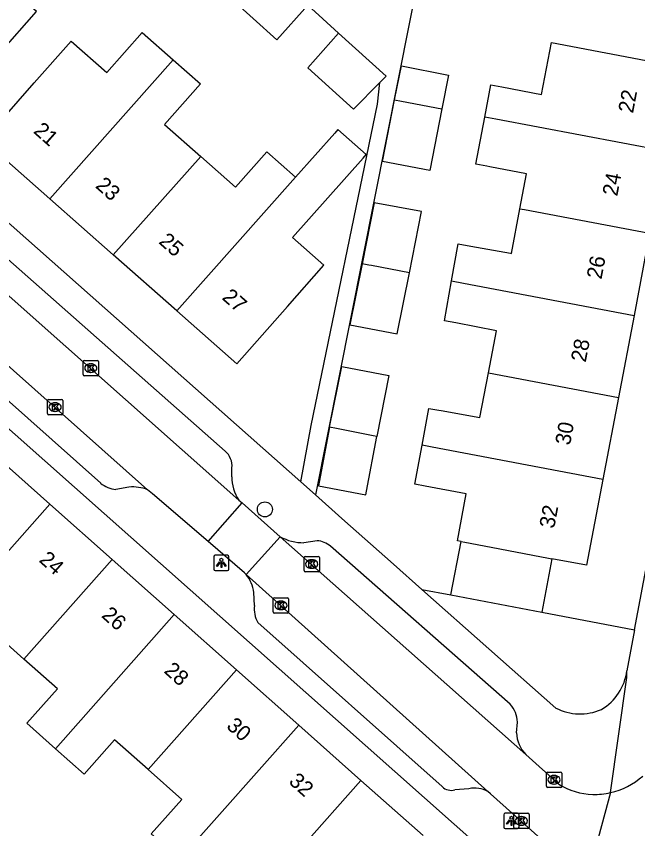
# Model space of a CAD drawing. Extents: x 163150 to 163546, y 380933 to 381635.
# Drawn here: x 163394.1 to 163434.7, y 381038.6 to 381091.7 of the extents above; entities that cross this region are included whole.
import ezdxf

# ---------------------------------------------------------------- set-up
doc = ezdxf.new("R2010")
doc.units = 0
for name, color, linetype in [('IMGEO_Boom', 7, 'Continuous'), ('IMGEO_Groenvoorziening', 7, 'Continuous'), ('IMGEO_Kolk', 7, 'Continuous'), ('IMGEO_Lichtpunt', 7, 'Continuous'), ('IMGEO_Muur', 7, 'Continuous'), ('IMGEO_Pand', 7, 'Continuous'), ('IMGEO_Pand_nummerreeks', 7, 'Continuous'), ('IMGEO_Rijbaan_lokaal_open', 7, 'Continuous'), ('IMGEO_Voetpad_open', 7, 'Continuous')]:
    doc.layers.add(name, color=color, linetype=linetype)

msp = doc.modelspace()

# ---------------------------------------------------------------- linework, layer by layer
at = {"layer": 'IMGEO_Boom'}
msp.add_circle((163410.34, 381059.48), 0.489, dxfattribs=at)
at = {"layer": 'IMGEO_Groenvoorziening'}
for points in [[(163420.6, 381054.259), (163422.486, 381053.901)], [(163428.425, 381052.773), (163434.486, 381051.622)]]:
    msp.add_lwpolyline(points, dxfattribs=at)
at = {"layer": 'IMGEO_Kolk'}
for p, q in [((163398.475, 381068.275), (163398.475, 381069.127)), ((163398.55, 381069.201), (163399.402, 381069.201)), ((163398.963, 381068.981), (163398.988, 381068.981)), ((163399.476, 381069.127), (163399.476, 381068.275)), ((163398.986, 381068.421), (163398.961, 381068.421)), ((163399.402, 381068.201), (163398.55, 381068.201)), ((163396.142, 381065.73), (163396.142, 381066.582)), ((163396.217, 381066.656), (163397.069, 381066.656)), ((163396.63, 381066.436), (163396.655, 381066.436)), ((163397.143, 381066.582), (163397.143, 381065.73)), ((163396.653, 381065.876), (163396.628, 381065.876)), ((163397.069, 381065.656), (163396.217, 381065.656)), ((163412.897, 381055.49), (163412.897, 381056.342)), ((163412.972, 381056.416), (163413.824, 381056.416)), ((163413.385, 381056.196), (163413.41, 381056.196)), ((163413.898, 381056.342), (163413.898, 381055.49)), ((163413.824, 381055.416), (163412.972, 381055.416)), ((163413.408, 381055.636), (163413.383, 381055.636)), ((163410.891, 381052.791), (163410.891, 381053.643)), ((163410.966, 381053.717), (163411.818, 381053.717)), ((163411.892, 381053.643), (163411.892, 381052.791)), ((163411.379, 381053.497), (163411.404, 381053.497)), ((163411.818, 381052.717), (163410.966, 381052.717)), ((163411.402, 381052.937), (163411.377, 381052.937)), ((163428.722, 381041.409), (163428.722, 381042.261)), ((163428.797, 381042.335), (163429.649, 381042.335)), ((163429.21, 381042.115), (163429.235, 381042.115)), ((163429.723, 381042.261), (163429.723, 381041.409)), ((163429.233, 381041.555), (163429.208, 381041.555)), ((163429.649, 381041.335), (163428.797, 381041.335)), ((163426.589, 381038.723), (163426.589, 381039.575)), ((163426.664, 381039.649), (163427.516, 381039.649)), ((163427.077, 381039.429), (163427.102, 381039.429)), ((163427.59, 381039.575), (163427.59, 381038.723)), ((163427.1, 381038.869), (163427.075, 381038.869)), ((163427.516, 381038.649), (163426.664, 381038.649))]:
    msp.add_line(p, q, dxfattribs=at)
for points in [[(163398.475, 381068.275), (163398.475, 381069.127)], [(163398.55, 381069.201), (163399.402, 381069.201)], [(163399.476, 381069.127), (163399.476, 381068.275)], [(163398.796, 381068.901), (163398.919, 381068.901), (163398.919, 381068.75), (163399.049, 381068.901), (163399.213, 381068.901), (163399.067, 381068.75), (163399.22, 381068.501), (163399.068, 381068.501), (163398.983, 381068.665), (163398.919, 381068.598), (163398.919, 381068.501), (163398.796, 381068.501), (163398.796, 381068.901)], [(163399.402, 381068.201), (163398.55, 381068.201)], [(163396.142, 381065.73), (163396.142, 381066.582)], [(163396.217, 381066.656), (163397.069, 381066.656)], [(163396.463, 381066.356), (163396.586, 381066.356), (163396.586, 381066.205), (163396.716, 381066.356), (163396.88, 381066.356), (163396.734, 381066.205), (163396.887, 381065.956), (163396.735, 381065.956), (163396.65, 381066.12), (163396.586, 381066.053), (163396.586, 381065.956), (163396.463, 381065.956), (163396.463, 381066.356)], [(163397.143, 381066.582), (163397.143, 381065.73)], [(163397.069, 381065.656), (163396.217, 381065.656)], [(163412.897, 381055.49), (163412.897, 381056.342)], [(163412.972, 381056.416), (163413.824, 381056.416)], [(163413.898, 381056.342), (163413.898, 381055.49)], [(163413.218, 381056.116), (163413.341, 381056.116), (163413.341, 381055.965), (163413.471, 381056.116), (163413.635, 381056.116), (163413.489, 381055.965), (163413.642, 381055.716), (163413.49, 381055.716), (163413.405, 381055.88), (163413.341, 381055.813), (163413.341, 381055.716), (163413.218, 381055.716), (163413.218, 381056.116)], [(163413.824, 381055.416), (163412.972, 381055.416)], [(163410.891, 381052.791), (163410.891, 381053.643)], [(163410.966, 381053.717), (163411.818, 381053.717)], [(163411.892, 381053.643), (163411.892, 381052.791)], [(163411.212, 381053.417), (163411.335, 381053.417), (163411.335, 381053.266), (163411.465, 381053.417), (163411.629, 381053.417), (163411.483, 381053.266), (163411.636, 381053.017), (163411.484, 381053.017), (163411.399, 381053.181), (163411.335, 381053.114), (163411.335, 381053.017), (163411.212, 381053.017), (163411.212, 381053.417)], [(163411.818, 381052.717), (163410.966, 381052.717)], [(163428.722, 381041.409), (163428.722, 381042.261)], [(163428.797, 381042.335), (163429.649, 381042.335)], [(163429.043, 381042.035), (163429.166, 381042.035), (163429.166, 381041.884), (163429.296, 381042.035), (163429.46, 381042.035), (163429.314, 381041.884), (163429.467, 381041.635), (163429.315, 381041.635), (163429.23, 381041.799), (163429.166, 381041.732), (163429.166, 381041.635), (163429.043, 381041.635), (163429.043, 381042.035)], [(163429.723, 381042.261), (163429.723, 381041.409)], [(163429.649, 381041.335), (163428.797, 381041.335)], [(163426.589, 381038.723), (163426.589, 381039.575)], [(163426.664, 381039.649), (163427.516, 381039.649)], [(163426.91, 381039.349), (163427.033, 381039.349), (163427.033, 381039.198), (163427.163, 381039.349), (163427.327, 381039.349), (163427.181, 381039.198), (163427.334, 381038.949), (163427.182, 381038.949), (163427.097, 381039.113), (163427.033, 381039.046), (163427.033, 381038.949), (163426.91, 381038.949), (163426.91, 381039.349)], [(163427.59, 381039.575), (163427.59, 381038.723)], [(163427.516, 381038.649), (163426.664, 381038.649)]]:
    msp.add_lwpolyline(points, dxfattribs=at)
for centre, start, end in [((163398.552, 381069.125), 91.552, 178.448), ((163398.552, 381069.125), 91.552, 178.448), ((163399.4, 381069.125), 1.552, 88.448), ((163399.4, 381069.125), 1.552, 88.448), ((163398.552, 381068.277), 181.552, 268.448), ((163398.552, 381068.277), 181.552, 268.448), ((163399.4, 381068.277), 271.552, 358.448), ((163399.4, 381068.277), 271.552, 358.448), ((163396.219, 381066.58), 91.552, 178.448), ((163396.219, 381066.58), 91.552, 178.448), ((163397.067, 381066.58), 1.552, 88.448), ((163397.067, 381066.58), 1.552, 88.448), ((163396.219, 381065.732), 181.552, 268.448), ((163396.219, 381065.732), 181.552, 268.448), ((163397.067, 381065.732), 271.552, 358.448), ((163397.067, 381065.732), 271.552, 358.448), ((163412.974, 381056.34), 91.552, 178.448), ((163412.974, 381056.34), 91.552, 178.448), ((163413.822, 381056.34), 1.552, 88.448), ((163413.822, 381056.34), 1.552, 88.448), ((163412.974, 381055.492), 181.552, 268.448), ((163412.974, 381055.492), 181.552, 268.448), ((163413.822, 381055.492), 271.552, 358.448), ((163413.822, 381055.492), 271.552, 358.448), ((163410.968, 381053.641), 91.552, 178.448), ((163410.968, 381053.641), 91.552, 178.448), ((163411.816, 381053.641), 1.552, 88.448), ((163411.816, 381053.641), 1.552, 88.448), ((163410.968, 381052.793), 181.552, 268.448), ((163410.968, 381052.793), 181.552, 268.448), ((163411.816, 381052.793), 271.552, 358.448), ((163411.816, 381052.793), 271.552, 358.448), ((163428.799, 381042.259), 91.552, 178.448), ((163428.799, 381042.259), 91.552, 178.448), ((163429.647, 381042.259), 1.552, 88.448), ((163429.647, 381042.259), 1.552, 88.448), ((163428.799, 381041.411), 181.552, 268.448), ((163428.799, 381041.411), 181.552, 268.448), ((163429.647, 381041.411), 271.552, 358.448), ((163429.647, 381041.411), 271.552, 358.448), ((163426.666, 381039.573), 91.552, 178.448), ((163426.666, 381039.573), 91.552, 178.448), ((163427.514, 381039.573), 1.552, 88.448), ((163427.514, 381039.573), 1.552, 88.448), ((163426.666, 381038.725), 181.552, 268.448), ((163426.666, 381038.725), 181.552, 268.448), ((163427.514, 381038.725), 271.552, 358.448), ((163427.514, 381038.725), 271.552, 358.448)]:
    msp.add_arc(centre, 0.0765, start, end, dxfattribs=at)
for centre, major_axis, ratio, start_param, end_param in [((163398.962, 381068.701), (-0.387, 0.002), 0.722429, 4.712389, 7.853982), ((163398.987, 381068.701), (-0.39, 0.002), 0.717154, 1.570796, 4.712389), ((163396.629, 381066.156), (-0.387, 0.002), 0.722429, 4.712389, 7.853982), ((163396.654, 381066.156), (-0.39, 0.002), 0.717154, 1.570796, 4.712389), ((163413.384, 381055.916), (-0.387, 0.002), 0.722429, 4.712389, 7.853982), ((163413.409, 381055.916), (-0.39, 0.002), 0.717154, 1.570796, 4.712389), ((163411.378, 381053.217), (-0.387, 0.002), 0.722429, 4.712389, 7.853982), ((163411.403, 381053.217), (-0.39, 0.002), 0.717154, 1.570796, 4.712389), ((163429.209, 381041.835), (-0.387, 0.002), 0.722429, 4.712389, 7.853982), ((163429.234, 381041.835), (-0.39, 0.002), 0.717154, 1.570796, 4.712389), ((163427.076, 381039.149), (-0.387, 0.002), 0.722429, 4.712389, 7.853982), ((163427.101, 381039.149), (-0.39, 0.002), 0.717154, 1.570796, 4.712389)]:
    msp.add_ellipse(centre, major_axis=major_axis, ratio=ratio, start_param=start_param, end_param=end_param, dxfattribs=at)
at = {"layer": 'IMGEO_Lichtpunt'}
for p, q in [((163407.002, 381056.39), (163407.002, 381055.583)), ((163407.002, 381056.39), (163407.002, 381055.583)), ((163407.904, 381056.485), (163407.096, 381056.485)), ((163407.904, 381056.485), (163407.096, 381056.485)), ((163407.998, 381055.583), (163407.998, 381056.39)), ((163407.998, 381055.583), (163407.998, 381056.39)), ((163407.096, 381055.489), (163407.904, 381055.489)), ((163407.096, 381055.489), (163407.904, 381055.489)), ((163425.941, 381039.556), (163425.941, 381038.749)), ((163425.941, 381039.556), (163425.941, 381038.749)), ((163426.843, 381039.651), (163426.035, 381039.651)), ((163426.843, 381039.651), (163426.035, 381039.651)), ((163426.937, 381038.749), (163426.937, 381039.556)), ((163426.937, 381038.749), (163426.937, 381039.556)), ((163426.035, 381038.655), (163426.843, 381038.655)), ((163426.035, 381038.655), (163426.843, 381038.655))]:
    msp.add_line(p, q, dxfattribs=at)
for points in [[(163407.376, 381056.054), (163407.415, 381056.026), (163407.227, 381055.764), (163407.189, 381055.791), (163407.376, 381056.054)], [(163407.478, 381056.006), (163407.525, 381056.006), (163407.525, 381055.684), (163407.478, 381055.684), (163407.478, 381056.006)], [(163407.588, 381056.026), (163407.626, 381056.053), (163407.813, 381055.791), (163407.774, 381055.763), (163407.588, 381056.026)], [(163426.315, 381039.22), (163426.354, 381039.192), (163426.166, 381038.93), (163426.128, 381038.957), (163426.315, 381039.22)], [(163426.417, 381039.172), (163426.464, 381039.172), (163426.464, 381038.85), (163426.417, 381038.85), (163426.417, 381039.172)], [(163426.527, 381039.192), (163426.565, 381039.219), (163426.752, 381038.957), (163426.713, 381038.929), (163426.527, 381039.192)]]:
    msp.add_lwpolyline(points, dxfattribs=at)
for centre in [(163407.501, 381056.188), (163426.44, 381039.354)]:
    msp.add_circle(centre, 0.0994, dxfattribs=at)
for centre, start, end in [((163407.096, 381056.39), 90, 180), ((163407.096, 381056.39), 90, 180), ((163407.904, 381056.39), 0, 90), ((163407.904, 381056.39), 0, 90), ((163407.096, 381055.583), 180, 270), ((163407.096, 381055.583), 180, 270), ((163407.904, 381055.583), 270, 0), ((163407.904, 381055.583), 270, 360), ((163426.035, 381039.556), 90, 180), ((163426.035, 381039.556), 90, 180), ((163426.843, 381039.556), 0, 90), ((163426.843, 381039.556), 0, 90), ((163426.035, 381038.749), 180, 270), ((163426.035, 381038.749), 180, 270), ((163426.843, 381038.749), 270, 0), ((163426.843, 381038.749), 270, 360)]:
    msp.add_arc(centre, 0.0946, start, end, dxfattribs=at)
at = {"layer": 'IMGEO_Muur'}
msp.add_lwpolyline([(163415.366, 381058.896), (163418.735, 381055.912)], dxfattribs=at)
at = {"layer": 'IMGEO_Pand'}
for points in [[(163385.582, 381089.213), (163389.741, 381085.536), (163393.054, 381089.282), (163395.432, 381091.972), (163393.769, 381093.442), (163393.233, 381093.916), (163395.576, 381096.566), (163393.614, 381098.301)], [(163408.025, 381092.942), (163411.13, 381090.125), (163413.141, 381092.387)], [(163396.296, 381079.753), (163391.977, 381083.562), (163395.285, 381087.312), (163397.694, 381090.043), (163400.021, 381087.99), (163402.329, 381090.608), (163404.358, 381088.819)], [(163415.16, 381090.565), (163413.144, 381088.297), (163416.123, 381085.594), (163417.846, 381087.332)], [(163417.846, 381087.332), (163418.269, 381087.759), (163415.16, 381090.565)], [(163424.701, 381085.084), (163425.1, 381087.187), (163425.82, 381087.05), (163428.413, 381086.558), (163429.057, 381089.95), (163432.613, 381089.284), (163437.525, 381088.35), (163436.48, 381082.853)], [(163404.358, 381088.819), (163396.296, 381079.753)], [(163404.358, 381088.819), (163406.132, 381087.255), (163403.796, 381084.603), (163406.154, 381082.523)], [(163418.814, 381086.2), (163419.257, 381088.427), (163422.339, 381087.815), (163421.902, 381085.615)], [(163421.902, 381085.615), (163421.105, 381081.605), (163418.018, 381082.189), (163418.814, 381086.2)], [(163418.814, 381086.2), (163419.256, 381086.116), (163421.902, 381085.615)], [(163426.997, 381079.103), (163427.429, 381081.379), (163425.034, 381081.834), (163424.836, 381081.872), (163424.117, 381082.009), (163424.701, 381085.084)], [(163436.48, 381082.853), (163425.421, 381084.948), (163424.701, 381085.084)], [(163404.584, 381072.443), (163408.507, 381068.982), (163411.815, 381072.732), (163414.195, 381075.43), (163412.15, 381077.234), (163416.753, 381082.409), (163416.956, 381082.637), (163415.11, 381084.279), (163414.9, 381084.043), (163412.349, 381081.174)], [(163406.154, 381082.523), (163408.427, 381080.518), (163410.478, 381082.825), (163412.349, 381081.174)], [(163406.154, 381082.523), (163400.44, 381076.098)], [(163412.349, 381081.174), (163404.584, 381072.443)], [(163400.44, 381076.098), (163396.296, 381079.753)], [(163419.777, 381074.924), (163420.57, 381078.915), (163417.483, 381079.499), (163416.69, 381075.51)], [(163422.532, 381074.402), (163422.964, 381076.809), (163423.781, 381076.662), (163426.37, 381076.199), (163426.443, 381076.186), (163426.997, 381079.103)], [(163426.997, 381079.103), (163427.288, 381079.048), (163435.463, 381077.499)], [(163435.463, 381077.499), (163434.445, 381072.144)], [(163404.584, 381072.443), (163400.44, 381076.098)], [(163416.69, 381075.51), (163415.897, 381071.518), (163418.983, 381070.933), (163419.777, 381074.924)], [(163419.777, 381074.924), (163417.3, 381075.394), (163417.132, 381075.426), (163416.69, 381075.51)], [(163424.939, 381068.398), (163425.46, 381071.144), (163422.803, 381071.649), (163422.064, 381071.789), (163422.532, 381074.402)], [(163422.532, 381074.402), (163423.311, 381074.254), (163434.445, 381072.144)], [(163434.445, 381072.144), (163433.428, 381066.79)], [(163414.572, 381064.848), (163415.358, 381068.806), (163418.444, 381068.221), (163417.653, 381064.236)], [(163420.61, 381063.673), (163421.04, 381066.076), (163421.699, 381065.959), (163421.845, 381065.933), (163424.385, 381065.483), (163424.939, 381068.398)], [(163424.939, 381068.398), (163433.428, 381066.79)], [(163433.428, 381066.79), (163432.41, 381061.436)], [(163414.572, 381064.848), (163413.89, 381061.248), (163413.844, 381061.009), (163416.931, 381060.424), (163416.976, 381060.663), (163417.653, 381064.236)], [(163417.653, 381064.236), (163417.412, 381064.284), (163415.012, 381064.76), (163414.572, 381064.848)], [(163423.149, 381057.389), (163422.91, 381057.434), (163423.49, 381060.487), (163420.81, 381060.996), (163420.127, 381061.126), (163420.61, 381063.673)], [(163432.41, 381061.436), (163421.267, 381063.548), (163420.61, 381063.673)], [(163392.234, 381063.427), (163396.298, 381059.822)], [(163432.41, 381061.436), (163431.345, 381055.832), (163429.088, 381056.261)], [(163396.298, 381059.822), (163388.548, 381051.076)], [(163396.298, 381059.822), (163400.361, 381056.217)], [(163422.486, 381053.901), (163423.149, 381057.389)], [(163423.149, 381057.389), (163423.398, 381057.341), (163424.655, 381057.103), (163428.856, 381056.305), (163429.088, 381056.261)], [(163400.361, 381056.217), (163394.598, 381049.713)], [(163400.361, 381056.217), (163404.425, 381052.611)], [(163429.088, 381056.261), (163428.425, 381052.773)], [(163422.486, 381053.901), (163428.425, 381052.773)], [(163404.425, 381052.611), (163396.671, 381043.86)], [(163404.425, 381052.611), (163408.489, 381049.006)], [(163394.598, 381049.713), (163392.406, 381051.661), (163390.417, 381049.415), (163388.548, 381051.076)], [(163396.671, 381043.86), (163394.801, 381045.52), (163396.791, 381047.766), (163394.598, 381049.713)], [(163402.722, 381042.497), (163408.489, 381049.006)], [(163408.489, 381049.006), (163412.553, 381045.4)], [(163412.553, 381045.4), (163404.794, 381036.643)], [(163412.553, 381045.4), (163416.617, 381041.795)], [(163402.722, 381042.497), (163400.529, 381044.445), (163398.539, 381042.2), (163396.671, 381043.86)], [(163404.794, 381036.643), (163402.925, 381038.304), (163404.915, 381040.549), (163402.722, 381042.497)], [(163408.87, 381032.959), (163408.824, 381032.999), (163416.617, 381041.795)], [(163416.617, 381041.795), (163420.681, 381038.189)]]:
    msp.add_lwpolyline(points, dxfattribs=at)
at = {"layer": 'IMGEO_Rijbaan_lokaal_open'}
for points in [[(163389.921, 381076.681), (163408.639, 381060.085)], [(163402.686, 381060.759), (163387.932, 381073.845)], [(163406.637, 381057.379), (163402.997, 381060.496), (163402.686, 381060.759)], [(163408.639, 381060.085), (163408.848, 381059.9)], [(163406.637, 381057.379), (163408.848, 381059.9)], [(163408.848, 381059.9), (163411.331, 381057.699)], [(163409.114, 381055.234), (163409.019, 381055.339), (163406.637, 381057.379)], [(163411.331, 381057.699), (163409.114, 381055.234)], [(163427.371, 381043.474), (163411.331, 381057.699)], [(163409.114, 381055.234), (163424.908, 381041.074)], [(163429.543, 381041.548), (163427.371, 381043.474)], [(163431.364, 381035.276), (163430.742, 381035.835), (163427.947, 381038.346), (163425.074, 381040.927), (163424.908, 381041.074)], [(163432.904, 381040.995), (163431.364, 381035.276)]]:
    msp.add_lwpolyline(points, dxfattribs=at)
for centre, radius, start, end in [((163431.856, 381045.641), 4.762, 282.7183, 311.5777), ((163431.86, 381045.217), 4.34, 237.7284, 268.5592), ((163431.852, 381045.668), 4.79, 268.797, 282.6931)]:
    msp.add_arc(centre, radius, start, end, dxfattribs=at)
at = {"layer": 'IMGEO_Voetpad_open'}
for points in [[(163348.475, 381118.157), (163412.679, 381061.277)], [(163348.313, 381104.939), (163430.25, 381032.233)], [(163413.276, 381094.847), (163420.572, 381095.23), (163413.645, 381060.421)], [(163415.16, 381090.565), (163414.131, 381091.494), (163413.141, 381092.387)], [(163412.679, 381061.277), (163413.36, 381064.962), (163417.698, 381085.92), (163417.846, 381087.332)], [(163434.486, 381051.622), (163441.105, 381086.644)], [(163407.752, 381063.284), (163392.96, 381076.312)], [(163399.619, 381061.195), (163388.476, 381071.097)], [(163408.184, 381061.615), (163408.192, 381062.186)], [(163412.679, 381061.277), (163413.645, 381060.421)], [(163401.469, 381060.94), (163400.616, 381060.787)], [(163413.645, 381060.421), (163415.366, 381058.896), (163418.735, 381055.912), (163420.6, 381054.259)], [(163413.748, 381057.432), (163412.895, 381057.305)], [(163426.365, 381046.76), (163414.631, 381057.076)], [(163429.339, 381046.517), (163420.6, 381054.259)], [(163409.659, 381053.202), (163409.621, 381054.053)], [(163421.917, 381041.392), (163409.872, 381052.094)], [(163434.486, 381051.622), (163433.981, 381048.948)], [(163432.904, 381040.995), (163433.984, 381048.514), (163433.981, 381048.948)], [(163426.769, 381044.9), (163426.83, 381045.598)], [(163423.667, 381041.252), (163422.752, 381041.177)]]:
    msp.add_lwpolyline(points, dxfattribs=at)
for centre, radius, start, end in [((163406.923, 381062.315), 1.276, 354.214, 49.4608), ((163411.003, 381061.621), 2.819, 180.1177, 213.0057), ((163400.737, 381062.506), 1.723, 229.5286, 265.9599), ((163401.692, 381058.259), 2.69, 68.3227, 94.7585), ((163412.9, 381060.625), 3.32, 241.802, 269.9187), ((163413.65, 381055.916), 1.519, 49.7815, 86.3028), ((163407.465, 381053.827), 2.168, 5.9913, 40.4761), ((163411.657, 381053.012), 2.007, 174.5597, 207.2037), ((163430.589, 381049.373), 3.418, 300.322, 352.8651), ((163425.081, 381045.572), 1.749, 0.8458, 42.774), ((163430.928, 381049.622), 3.488, 242.9053, 293.4379), ((163429.075, 381045.033), 2.309, 183.3078, 222.4673), ((163422.516, 381041.988), 0.845, 224.887, 286.2347), ((163424.037, 381039.418), 1.871, 62.2658, 101.4093)]:
    msp.add_arc(centre, radius, start, end, dxfattribs=at)

# ---------------------------------------------------------------- texts
at = {"layer": 'IMGEO_Pand_nummerreeks'}
for s, rotation, p in [('22', 79.2401, (163434.38, 381085.296)), ('21', 318.5867, (163395.175, 381084.101)), ('23', 318.5867, (163399.223, 381080.53)), ('24', 79.2401, (163433.35, 381079.879)), ('25', 318.5867, (163403.356, 381076.885)), ('26', 79.2401, (163432.32, 381074.459)), ('27', 318.5866, (163407.488, 381073.24)), ('28', 79.2401, (163431.291, 381069.043)), ('30', 79.2401, (163430.261, 381063.623)), ('32', 79.2401, (163429.23, 381058.197)), ('24', 318.4212, (163395.541, 381056.108)), ('26', 318.4212, (163399.618, 381052.492)), ('28', 318.4212, (163403.697, 381048.873)), ('30', 318.4212, (163407.773, 381045.256)), ('32', 318.4205, (163411.846, 381041.643))]:
    msp.add_text(s, height=1, rotation=rotation, dxfattribs=at).set_placement(p)

doc.saveas('drawing.dxf')
